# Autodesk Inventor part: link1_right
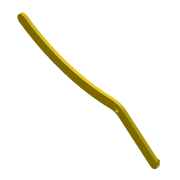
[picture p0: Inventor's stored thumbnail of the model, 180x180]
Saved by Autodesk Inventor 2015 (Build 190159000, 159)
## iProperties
Created: 2020-09
Part Number: link1_right
Material: 一般
Document SubType Name: Modeling
Designer: 徐冠倫
Mass: 167.388 g
Surface Area: 456.359 cm^2
Volume: 167.388 cm^3
Density: 1 g/cm^3
Appearance: 預設
Author: 徐冠倫
Author: IANNIAN
Title: D:\Desktop\OCW-Computer-Aided Engineering Drawing\OCW_Topic 06：組合圖與機構模擬(進階)\6-1_Flexibility\Mechanical Gripper(piston)\Mechanical Gripper(STP)\link1_right.stp
Creation Date: 2020-09-04
Sending System: Autodesk Inventor 2020
Preprocessor: ST-DEVELOPER v18
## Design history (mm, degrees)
node "link1_right1"
body "Solid1"
node "Base1"
